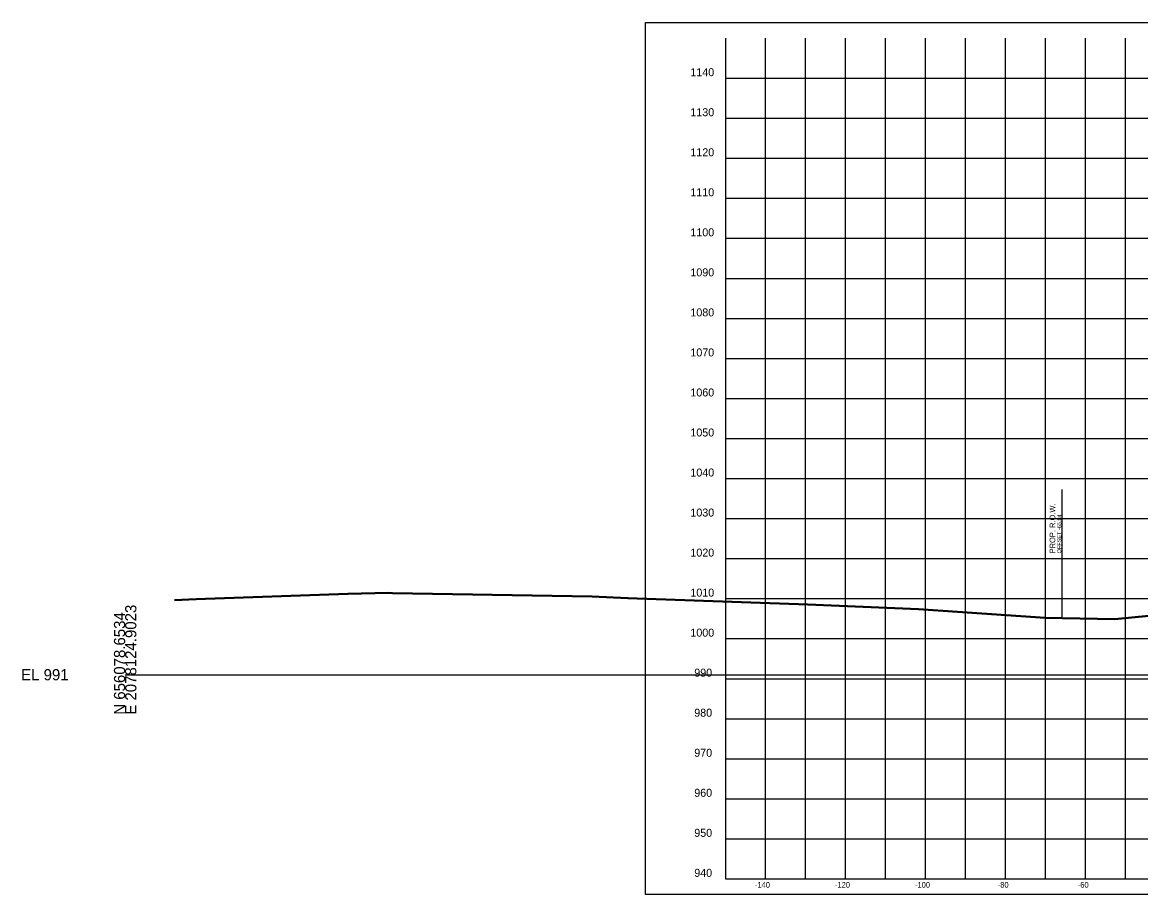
# Model space of a CAD drawing. Extents: x 5868 to 6683, y 2883 to 19120.
# Drawn here: x 5868.1 to 6147.5, y 11390.1 to 11608 of the extents above; entities that cross this region are included whole.
import ezdxf

# ---------------------------------------------------------------- set-up
doc = ezdxf.new("R2010")
doc.units = 0
for name, color, linetype in [('DESIGN - ROW - Right-of-Way and Easement Labels', 7, 'Continuous'), ('DESIGN - ROW - Right-of-Way Linework', 7, 'Continuous'), ('DESIGN - SHEET - Corner Text', 7, 'Continuous'), ('DESIGN - SHEET - Light Grid', 7, 'Continuous'), ('DESIGN - SHEET - Linework', 7, 'Continuous'), ('DESIGN - SHEET - Plot Shape', 7, 'Continuous'), ('SURVEY - GROUND - Bottom of Topsoil Layer', 7, 'Continuous'), ('SURVEY - GROUND - Top of Ground', 7, 'Continuous')]:
    doc.layers.add(name, color=color, linetype=linetype)

msp = doc.modelspace()

# ---------------------------------------------------------------- linework, layer by layer
at = {"layer": 'DESIGN - ROW - Right-of-Way Linework'}
msp.add_line((6127.95, 11459.37), (6127.95, 11491.37), dxfattribs=at)
at = {"layer": 'DESIGN - SHEET - Light Grid'}
msp.add_line((5893.78, 11445.07), (6193.78, 11445.07), dxfattribs=at)
at = {"layer": 'DESIGN - SHEET - Linework'}
for p, q in [((6053.78, 11394.07), (6053.78, 11604.07)), ((6063.78, 11394.07), (6063.78, 11604.07)), ((6073.78, 11394.07), (6073.78, 11604.07)), ((6083.78, 11394.07), (6083.78, 11604.07)), ((6093.78, 11394.07), (6093.78, 11604.07)), ((6103.78, 11394.07), (6103.78, 11604.07)), ((6113.78, 11394.07), (6113.78, 11604.07)), ((6123.78, 11394.07), (6123.78, 11604.07)), ((6133.78, 11394.07), (6133.78, 11604.07)), ((6143.78, 11394.07), (6143.78, 11604.07)), ((6043.78, 11594.07), (6343.78, 11594.07)), ((6043.78, 11584.07), (6343.78, 11584.07)), ((6043.78, 11574.07), (6343.78, 11574.07)), ((6043.78, 11564.07), (6343.78, 11564.07)), ((6043.78, 11554.07), (6343.78, 11554.07)), ((6043.78, 11544.07), (6343.78, 11544.07)), ((6043.78, 11534.07), (6343.78, 11534.07)), ((6043.78, 11524.07), (6343.78, 11524.07)), ((6043.78, 11514.07), (6343.78, 11514.07)), ((6043.78, 11504.07), (6343.78, 11504.07)), ((6043.78, 11494.07), (6343.78, 11494.07)), ((6043.78, 11484.07), (6343.78, 11484.07)), ((6043.78, 11474.07), (6343.78, 11474.07)), ((6043.78, 11464.07), (6343.78, 11464.07)), ((6043.78, 11454.07), (6343.78, 11454.07)), ((6043.78, 11444.07), (6343.78, 11444.07)), ((6043.78, 11434.07), (6343.78, 11434.07)), ((6043.78, 11424.07), (6343.78, 11424.07)), ((6043.78, 11414.07), (6343.78, 11414.07)), ((6043.78, 11404.07), (6343.78, 11404.07))]:
    msp.add_line(p, q, dxfattribs=at)
msp.add_lwpolyline([(6043.78, 11604.07), (6043.78, 11394.07), (6343.78, 11394.07), (6343.78, 11604.07)], dxfattribs=at)
at = {"layer": 'DESIGN - SHEET - Plot Shape'}
msp.add_lwpolyline([(6023.78, 11608.01), (6363.78, 11608.01), (6363.78, 11390.13), (6023.78, 11390.13)], close=True, dxfattribs=at)
at = {"layer": 'SURVEY - GROUND - Bottom of Topsoil Layer'}
for p, q in [((5906.11, 11463.6), (5911.53, 11463.87)), ((5911.53, 11463.87), (5949.41, 11465.21)), ((5949.41, 11465.21), (5959.56, 11465.4)), ((5959.56, 11465.4), (5960.62, 11465.36)), ((5960.62, 11465.36), (6010.5, 11464.49)), ((6010.5, 11464.49), (6019.39, 11464.07)), ((6019.39, 11464.07), (6064.39, 11462.52)), ((6064.39, 11462.52), (6092.05, 11461.33)), ((6092.05, 11461.33), (6123.68, 11459.2)), ((6123.68, 11459.2), (6141.09, 11458.89)), ((6141.09, 11458.89), (6153.84, 11460.12))]:
    msp.add_line(p, q, dxfattribs=at)
at = {"layer": 'SURVEY - GROUND - Top of Ground'}
msp.add_lwpolyline([(5906.11, 11463.85), (5911.53, 11464.12), (5949.41, 11465.46), (5959.56, 11465.65), (5960.62, 11465.61), (6010.5, 11464.74), (6019.39, 11464.32), (6064.39, 11462.77), (6092.05, 11461.58), (6123.68, 11459.45), (6141.09, 11459.14), (6153.84, 11460.37)], dxfattribs=at)

# ---------------------------------------------------------------- texts
at = {"layer": 'DESIGN - ROW - Right-of-Way and Easement Labels'}
for s, height, p in [('PROP. R.O.W.', 1.4, (6126.2, 11475.37)), ('OFFSET -65.84', 1, (6127.7, 11475.37))]:
    msp.add_text(s, height=height, rotation=90, dxfattribs=at).set_placement(p)
at = {"layer": 'DESIGN - SHEET - Corner Text'}
for s, height, p in [('1140', 2, (6035.03, 11594.57)), ('1130', 2, (6035.03, 11584.57)), ('1120', 2, (6035.03, 11574.57)), ('1110', 2, (6035.03, 11564.57)), ('1100', 2, (6035.03, 11554.57)), ('1090', 2, (6035.03, 11544.57)), ('1080', 2, (6035.03, 11534.57)), ('1070', 2, (6035.03, 11524.57)), ('1060', 2, (6035.03, 11514.57)), ('1050', 2, (6035.03, 11504.57)), ('1040', 2, (6035.03, 11494.57)), ('1030', 2, (6035.03, 11484.57)), ('1020', 2, (6035.03, 11474.57)), ('1010', 2, (6035.03, 11464.57)), ('1000', 2, (6035.03, 11454.57)), ('990', 2, (6036, 11444.57)), ('980', 2, (6036, 11434.57)), ('970', 2, (6036, 11424.57)), ('960', 2, (6036, 11414.57)), ('950', 2, (6036, 11404.57)), ('940', 2, (6036, 11394.57)), ('-140', 1.4, (6051.16, 11391.87)), ('-120', 1.4, (6071.16, 11391.87)), ('-100', 1.4, (6091.16, 11391.87)), ('-80', 1.4, (6111.84, 11391.87)), ('-60', 1.4, (6131.84, 11391.87))]:
    msp.add_text(s, height=height, dxfattribs=at).set_placement(p)
at = {"layer": 'DESIGN - SHEET - Light Grid'}
for s, p in [('N 656078.6534', (5893.78, 11435.07)), ('E 2078124.9023', (5896.58, 11435.07))]:
    msp.add_text(s, height=2.8, rotation=90, dxfattribs=at).set_placement(p)
msp.add_text('EL 991', height=2.8, dxfattribs=at).set_placement((5867.78, 11443.67))

doc.saveas('drawing.dxf')
